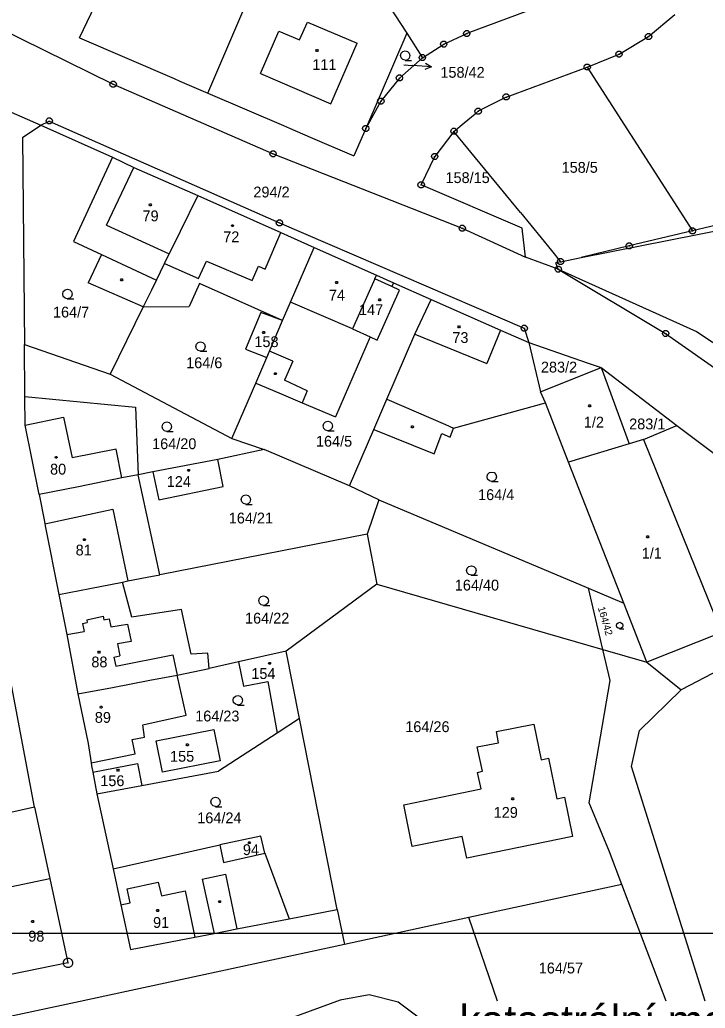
# Model space of a CAD drawing. Extents: x -779723 to -777378, y -1011169 to -1009297.
# Drawn here: x -779371.6 to -779263.9, y -1010279.6 to -1010124.4 of the extents above; entities that cross this region are included whole.
import ezdxf

# ---------------------------------------------------------------- set-up
doc = ezdxf.new("R2010")
doc.units = 0
for name, color, linetype in [('Default', 7, 'Continuous'), ('KN_HRANICE', 7, 'Continuous'), ('KN_KULTURY', 7, 'Continuous'), ('KN_PARCELY', 7, 'Continuous'), ('KN_SLUCKY', 7, 'Continuous'), ('LEGENDA', 7, 'Continuous')]:
    doc.layers.add(name, color=color, linetype=linetype)

# ---------------------------------------------------------------- blocks, each defined once
blk = doc.blocks.new('101')
at = {"layer": 'Default'}
blk.add_line((-0.05, 0), (0.05, 0), dxfattribs=at)
blk.add_lwpolyline([(0.19, 0.72), (0.53, 0.53), (0.72, 0.19), (0.72, -0.2), (0.53, -0.54), (0.19, -0.73), (-0.2, -0.73), (-0.54, -0.54), (-0.73, -0.2), (-0.73, 0.19), (-0.54, 0.53), (-0.2, 0.72), (0.19, 0.72)], dxfattribs=at)
blk = doc.blocks.new('304')
at = {"layer": 'Default'}
blk.add_lwpolyline([(0, 0), (-0.38, 0.1), (-0.65, 0.37), (-0.75, 0.74), (-0.65, 1.11), (-0.38, 1.38), (-0.01, 1.48), (0.36, 1.38), (0.63, 1.11), (0.73, 0.73), (0.63, 0.35), (0.36, 0.08), (-0.02, -0.02), (0.98, -0.02)], dxfattribs=at)
blk = doc.blocks.new('10292')
at = {"layer": 'Default'}
blk.add_line((0, 3), (0, 0), dxfattribs=at)
blk.add_lwpolyline([(-0.5, 2), (0, 3), (0.5, 2)], dxfattribs=at)
blk = doc.blocks.new('402')
at = {"layer": 'Default'}
blk.add_lwpolyline([(0.09, 0.15), (0.18, 0), (0.09, -0.15), (-0.09, -0.15), (-0.18, 0), (-0.09, 0.15), (0.09, 0.15)], dxfattribs=at)
blk = doc.blocks.new('105')
at = {"layer": 'Default'}
blk.add_line((-0.12, 0), (0.12, 0), dxfattribs=at)
blk.add_lwpolyline([(0.15, 0.48), (0.4, 0.3), (0.5, 0.01), (0.4, -0.28), (0.15, -0.46), (-0.16, -0.46), (-0.41, -0.28), (-0.51, 0.01), (-0.41, 0.3), (-0.16, 0.48), (0.15, 0.48)], dxfattribs=at)

msp = doc.modelspace()

# ---------------------------------------------------------------- linework, layer by layer
at = {"layer": 'KN_HRANICE'}
for p, q in [((-779362.17, -1010127.2), (-779340.06, -1010080.85)), ((-779342.01, -1010135.87), (-779327.06, -1010101.1)), ((-779327.06, -1010101.1), (-779310.76, -1010126.49)), ((-779288.77, -1010121.88), (-779301.33, -1010126.54)), ((-779380.8, -1010122.72), (-779356.88, -1010134.5)), ((-779272.77, -1010127.01), (-779268.62, -1010123.54)), ((-779327.61, -1010127.53), (-779326.36, -1010124.72)), ((-779326.36, -1010124.72), (-779318.57, -1010128.06)), ((-779333.75, -1010132.81), (-779330.83, -1010126.13)), ((-779330.83, -1010126.13), (-779327.61, -1010127.53)), ((-779310.76, -1010126.49), (-779317.19, -1010141.44)), ((-779310.76, -1010126.49), (-779308.3, -1010130.32)), ((-779304.94, -1010128.18), (-779301.33, -1010126.54)), ((-779277.41, -1010129.77), (-779272.77, -1010127.01)), ((-779308.3, -1010130.32), (-779304.94, -1010128.18)), ((-779282.4, -1010131.79), (-779277.41, -1010129.77)), ((-779308.3, -1010130.32), (-779311.9, -1010133.51)), ((-779295.13, -1010136.5), (-779282.4, -1010131.79)), ((-779282.4, -1010131.79), (-779265.87, -1010157.54)), ((-779356.88, -1010134.5), (-779331.75, -1010145.42)), ((-779311.9, -1010133.51), (-779314.82, -1010137.15)), ((-779379.75, -1010135.84), (-779368.25, -1010140.93)), ((-779314.82, -1010137.15), (-779317.19, -1010141.44)), ((-779295.13, -1010136.5), (-779299.54, -1010138.73)), ((-779301.73, -1010140.55), (-779300, -1010139.11)), ((-779300, -1010139.11), (-779299.54, -1010138.73)), ((-779371.12, -1010142.88), (-779368.25, -1010140.93)), ((-779368.25, -1010140.93), (-779356.99, -1010145.94)), ((-779303.34, -1010141.89), (-779301.73, -1010140.55)), ((-779317.19, -1010141.44), (-779319.05, -1010145.75)), ((-779303.34, -1010141.89), (-779306.36, -1010145.83)), ((-779292.91, -1010154.64), (-779303.34, -1010141.89)), ((-779371.12, -1010142.88), (-779370.81, -1010175.38)), ((-779331.75, -1010145.42), (-779302.03, -1010157.12)), ((-779356.99, -1010145.94), (-779363.09, -1010159.19)), ((-779356.99, -1010145.94), (-779353.64, -1010147.57)), ((-779308.49, -1010150.3), (-779306.36, -1010145.83)), ((-779353.64, -1010147.57), (-779343.57, -1010151.97)), ((-779225.76, -1010148.05), (-779265.87, -1010157.54)), ((-779292.63, -1010157.12), (-779308.49, -1010150.3)), ((-779283.36, -1010161.68), (-779225.71, -1010150.28)), ((-779343.57, -1010151.97), (-779346.34, -1010157.62)), ((-779343.57, -1010151.97), (-779330.56, -1010157.78)), ((-779292.91, -1010154.64), (-779288.01, -1010160.63)), ((-779346.34, -1010157.62), (-779348.07, -1010161.15)), ((-779330.56, -1010157.78), (-779325.31, -1010160.13)), ((-779302.03, -1010157.12), (-779292.12, -1010161.67)), ((-779292.12, -1010161.67), (-779292.63, -1010157.12)), ((-779265.87, -1010157.54), (-779275.8, -1010159.89)), ((-779363.09, -1010159.19), (-779358.72, -1010161.22)), ((-779348.79, -1010162.63), (-779348.07, -1010161.15)), ((-779329.01, -1010168.72), (-779325.31, -1010160.13)), ((-779325.31, -1010160.13), (-779315.53, -1010164.48)), ((-779288.01, -1010160.63), (-779286.59, -1010162.36)), ((-779275.8, -1010159.89), (-779283.36, -1010161.68)), ((-779358.72, -1010161.22), (-779360.82, -1010165.67)), ((-779350.07, -1010165.25), (-779348.79, -1010162.63)), ((-779286.95, -1010163.54), (-779292.12, -1010161.67)), ((-779286.59, -1010162.36), (-779287.32, -1010162.52)), ((-779286.95, -1010163.54), (-779287.32, -1010162.52)), ((-779286.59, -1010162.36), (-779283.36, -1010161.68)), ((-779286.95, -1010163.54), (-779270.09, -1010173.63)), ((-779286.95, -1010163.54), (-779265.26, -1010173.35)), ((-779352.15, -1010169.47), (-779360.82, -1010165.67)), ((-779350.37, -1010165.85), (-779350.86, -1010166.85)), ((-779350.07, -1010165.25), (-779350.37, -1010165.85)), ((-779343.34, -1010165.79), (-779344.96, -1010169.41)), ((-779330.25, -1010171.61), (-779343.34, -1010165.79)), ((-779315.79, -1010165.07), (-779319.28, -1010172.9)), ((-779313.09, -1010166.28), (-779315.79, -1010165.07)), ((-779315.53, -1010164.48), (-779312.82, -1010165.66)), ((-779312.82, -1010165.66), (-779313.09, -1010166.28)), ((-779312.82, -1010165.66), (-779306.92, -1010168.28)), ((-779350.86, -1010166.85), (-779352.15, -1010169.47)), ((-779315.38, -1010174.67), (-779311.89, -1010166.81)), ((-779311.89, -1010166.81), (-779313.09, -1010166.28)), ((-779330.25, -1010171.61), (-779329.01, -1010168.72)), ((-779309.48, -1010173.73), (-779306.92, -1010168.28)), ((-779306.92, -1010168.28), (-779296.03, -1010173.11)), ((-779352.15, -1010169.47), (-779357.33, -1010180.05)), ((-779352.15, -1010169.47), (-779344.96, -1010169.41)), ((-779332.31, -1010176.42), (-779330.25, -1010171.61)), ((-779319.28, -1010172.9), (-779316.5, -1010174.16)), ((-779296.03, -1010173.11), (-779291.6, -1010175.07)), ((-779265.26, -1010173.35), (-779254.75, -1010180.24)), ((-779316.5, -1010174.16), (-779321.95, -1010186.72)), ((-779316.5, -1010174.16), (-779315.38, -1010174.67)), ((-779313.9, -1010183.97), (-779309.48, -1010173.73)), ((-779291.6, -1010175.07), (-779289.74, -1010182.83)), ((-779270.09, -1010173.63), (-779257.16, -1010182.76)), ((-779370.73, -1010183.55), (-779370.81, -1010175.38)), ((-779370.81, -1010175.38), (-779357.33, -1010180.05)), ((-779332.74, -1010177.43), (-779332.31, -1010176.42)), ((-779334.46, -1010181.43), (-779332.74, -1010177.43)), ((-779289.74, -1010182.83), (-779280.19, -1010178.98)), ((-779280.19, -1010178.98), (-779268.33, -1010188.11)), ((-779280.19, -1010178.98), (-779275.82, -1010190.98)), ((-779357.33, -1010180.05), (-779338.22, -1010190.12)), ((-779338.22, -1010190.12), (-779334.46, -1010181.43)), ((-779334.46, -1010181.43), (-779330.86, -1010182.95)), ((-779288.98, -1010184.55), (-779289.74, -1010182.83)), ((-779370.69, -1010188.04), (-779370.73, -1010183.55)), ((-779370.73, -1010183.55), (-779353.39, -1010185.24)), ((-779330.86, -1010182.95), (-779327.18, -1010184.51)), ((-779315.95, -1010188.73), (-779313.9, -1010183.97)), ((-779353.39, -1010185.24), (-779352.97, -1010195.83)), ((-779327.18, -1010184.51), (-779321.95, -1010186.72)), ((-779303.42, -1010188.49), (-779288.98, -1010184.55)), ((-779285.33, -1010193.87), (-779288.98, -1010184.55)), ((-779368.51, -1010198.95), (-779370.69, -1010188.04)), ((-779319.77, -1010197.59), (-779315.95, -1010188.73)), ((-779315.95, -1010188.73), (-779306.46, -1010192.53)), ((-779303.95, -1010189.91), (-779303.42, -1010188.49)), ((-779273.57, -1010190.29), (-779268.33, -1010188.11)), ((-779268.33, -1010188.11), (-779262.24, -1010192.63)), ((-779338.22, -1010190.12), (-779333.16, -1010191.86)), ((-779306.46, -1010192.53), (-779305.24, -1010189.37)), ((-779305.24, -1010189.37), (-779303.95, -1010189.91)), ((-779273.57, -1010190.29), (-779275.82, -1010190.98)), ((-779273.57, -1010190.29), (-779261.29, -1010220.59)), ((-779333.16, -1010191.86), (-779340.44, -1010193.45)), ((-779319.77, -1010197.59), (-779333.16, -1010191.86)), ((-779275.82, -1010190.98), (-779285.33, -1010193.87)), ((-779340.44, -1010193.45), (-779350.63, -1010195.35)), ((-779339.6, -1010197.69), (-779340.44, -1010193.45)), ((-779350.63, -1010195.35), (-779352.97, -1010195.83)), ((-779350.63, -1010195.35), (-779349.69, -1010199.77)), ((-779276.66, -1010216.01), (-779285.33, -1010193.87)), ((-779355.52, -1010196.34), (-779362.33, -1010197.71)), ((-779352.97, -1010195.83), (-779355.52, -1010196.34)), ((-779349.54, -1010211.54), (-779352.97, -1010195.83)), ((-779362.33, -1010197.71), (-779368.51, -1010198.95)), ((-779349.69, -1010199.77), (-779339.6, -1010197.69)), ((-779315.16, -1010199.77), (-779319.77, -1010197.59)), ((-779315.16, -1010199.77), (-779317, -1010205.16)), ((-779315.16, -1010199.77), (-779282.2, -1010213.67)), ((-779317, -1010205.16), (-779349.54, -1010211.54)), ((-779317, -1010205.16), (-779315.47, -1010213.01)), ((-779354.59, -1010212.5), (-779351.55, -1010211.93)), ((-779351.55, -1010211.93), (-779349.54, -1010211.54)), ((-779365.42, -1010214.66), (-779360.52, -1010213.7)), ((-779360.52, -1010213.7), (-779355.42, -1010212.7)), ((-779355.42, -1010212.7), (-779354.59, -1010212.5)), ((-779353.94, -1010218.2), (-779355.42, -1010212.7)), ((-779315.47, -1010213.01), (-779329.68, -1010223.56)), ((-779315.47, -1010213.01), (-779279.96, -1010223.28)), ((-779282.2, -1010213.67), (-779276.66, -1010216.01)), ((-779279.96, -1010223.28), (-779282.2, -1010213.67)), ((-779365.42, -1010214.66), (-779364.16, -1010220.93)), ((-779346.13, -1010216.99), (-779353.94, -1010218.2)), ((-779344.62, -1010224.02), (-779346.13, -1010216.99)), ((-779273.03, -1010225.28), (-779276.66, -1010216.01)), ((-779364.16, -1010220.93), (-779362.43, -1010230.27)), ((-779261.29, -1010220.59), (-779273.03, -1010225.28)), ((-779250.45, -1010220.64), (-779267.64, -1010229.61)), ((-779279.96, -1010223.28), (-779273.03, -1010225.28)), ((-779278.82, -1010228.15), (-779279.96, -1010223.28)), ((-779342.02, -1010223.87), (-779344.62, -1010224.02)), ((-779341.78, -1010226.26), (-779342.02, -1010223.87)), ((-779329.68, -1010223.56), (-779337.17, -1010225.23)), ((-779327.59, -1010234.13), (-779329.68, -1010223.56)), ((-779346.83, -1010227.29), (-779341.78, -1010226.26)), ((-779337.17, -1010225.23), (-779341.78, -1010226.26)), ((-779273.03, -1010225.28), (-779267.64, -1010229.61)), ((-779351.1, -1010228.1), (-779346.83, -1010227.29)), ((-779369.26, -1010248.05), (-779372.96, -1010228.31)), ((-779362.43, -1010230.27), (-779356.99, -1010229.23)), ((-779356.99, -1010229.23), (-779351.1, -1010228.1)), ((-779282.1, -1010247.39), (-779278.82, -1010228.15)), ((-779362.43, -1010230.27), (-779360.81, -1010238.06)), ((-779274.18, -1010236), (-779267.64, -1010229.61)), ((-779327.59, -1010234.13), (-779331.1, -1010236.4)), ((-779321.68, -1010264.11), (-779327.59, -1010234.13)), ((-779296.68, -1010236.16), (-779290.77, -1010235.01)), ((-779290.77, -1010235.01), (-779289.63, -1010240.6)), ((-779331.1, -1010236.4), (-779340.34, -1010242.39)), ((-779296.34, -1010237.93), (-779296.68, -1010236.16)), ((-779275.45, -1010241.64), (-779274.18, -1010236)), ((-779360.81, -1010238.06), (-779360.33, -1010241.1)), ((-779299.67, -1010238.58), (-779296.34, -1010237.93)), ((-779298.86, -1010242.42), (-779299.67, -1010238.58)), ((-779289.63, -1010240.6), (-779288.47, -1010240.36)), ((-779288.47, -1010240.36), (-779287.16, -1010246.73)), ((-779360.33, -1010241.1), (-779360.26, -1010241.57)), ((-779360.26, -1010241.57), (-779360.07, -1010242.55)), ((-779263.9, -1010278.51), (-779275.45, -1010241.64)), ((-779360.07, -1010242.55), (-779359.42, -1010245.98)), ((-779352.38, -1010244.66), (-779340.34, -1010242.39)), ((-779299.63, -1010242.58), (-779298.86, -1010242.42)), ((-779299.09, -1010245.15), (-779299.63, -1010242.58)), ((-779359.42, -1010245.98), (-779352.38, -1010244.66)), ((-779359.42, -1010245.98), (-779356.9, -1010257.72)), ((-779311.24, -1010247.7), (-779299.09, -1010245.15)), ((-779287.16, -1010246.73), (-779285.99, -1010246.49)), ((-779285.99, -1010246.49), (-779284.72, -1010252.66)), ((-779369.26, -1010248.05), (-779389.34, -1010252.55)), ((-779369.26, -1010248.05), (-779366.85, -1010259.23)), ((-779309.89, -1010254.22), (-779311.24, -1010247.7)), ((-779278.89, -1010255.08), (-779282.1, -1010247.39)), ((-779333.7, -1010252.59), (-779340.13, -1010253.99)), ((-779333.07, -1010255.29), (-779333.7, -1010252.59)), ((-779302.06, -1010252.64), (-779309.89, -1010254.22)), ((-779301.34, -1010256.04), (-779302.06, -1010252.64)), ((-779284.72, -1010252.66), (-779301.34, -1010256.04)), ((-779356.9, -1010257.72), (-779340.13, -1010253.99)), ((-779340.13, -1010253.99), (-779339.57, -1010256.76)), ((-779339.57, -1010256.76), (-779333.07, -1010255.29)), ((-779333.07, -1010255.29), (-779329.22, -1010265.58)), ((-779276.95, -1010260.2), (-779278.89, -1010255.08)), ((-779356.9, -1010257.72), (-779355.68, -1010263.39)), ((-779375.67, -1010261.12), (-779366.85, -1010259.23)), ((-779366.85, -1010259.23), (-779363.99, -1010272.5)), ((-779276.95, -1010260.2), (-779300.99, -1010265.39)), ((-779270, -1010278.51), (-779276.95, -1010260.2)), ((-779355.68, -1010263.39), (-779354.17, -1010270.43)), ((-779329.22, -1010265.58), (-779321.68, -1010264.11)), ((-779321.68, -1010264.11), (-779320.52, -1010269.6)), ((-779337.47, -1010267.18), (-779329.22, -1010265.58)), ((-779300.99, -1010265.39), (-779320.52, -1010269.6)), ((-779296.52, -1010278.51), (-779300.99, -1010265.39)), ((-779344.05, -1010268.46), (-779341.01, -1010267.87)), ((-779341.01, -1010267.87), (-779337.47, -1010267.18)), ((-779320.52, -1010269.6), (-779362.78, -1010278.71)), ((-779354.17, -1010270.43), (-779344.05, -1010268.46)), ((-779363.99, -1010272.5), (-779372.96, -1010274.36)), ((-779316.65, -1010277.51), (-779321.24, -1010278.36)), ((-779312.1, -1010278.67), (-779316.65, -1010277.51)), ((-779362.78, -1010278.71), (-779411.57, -1010289.24)), ((-779321.24, -1010278.36), (-779338.14, -1010284.55)), ((-779308.36, -1010281.51), (-779312.1, -1010278.67))]:
    msp.add_line(p, q, dxfattribs=at)
for points in [[(-779362.17, -1010127.2), (-779347.32, -1010133.59), (-779346.4, -1010133.98), (-779342.01, -1010135.87)], [(-779333.75, -1010132.81), (-779322.68, -1010137.57), (-779318.57, -1010128.06)], [(-779342.01, -1010135.87), (-779330.11, -1010140.99), (-779329.19, -1010141.39), (-779325.94, -1010142.79), (-779319.05, -1010145.75)], [(-779330.25, -1010171.61), (-779333.7, -1010170.34), (-779336.07, -1010176.09), (-779332.74, -1010177.43)], [(-779291.6, -1010175.07), (-779282.25, -1010178.28), (-779280.19, -1010178.98)], [(-779368.51, -1010198.95), (-779367.68, -1010203.17), (-779367.63, -1010203.52)], [(-779367.63, -1010203.52), (-779367.55, -1010203.87), (-779365.42, -1010214.66)], [(-779337.17, -1010225.23), (-779336.4, -1010229.03), (-779332.59, -1010228.29), (-779331.1, -1010236.4)], [(-779360.33, -1010241.1), (-779353.42, -1010239.67), (-779353.88, -1010237.43), (-779351.94, -1010237.03), (-779352.2, -1010235.13), (-779345.41, -1010233.6), (-779346.83, -1010227.29)], [(-779360.07, -1010242.55), (-779353.08, -1010241.18), (-779352.38, -1010244.66)]]:
    msp.add_lwpolyline(points, dxfattribs=at)
msp.add_lwpolyline([(-779350.1, -1010237.63), (-779341.04, -1010235.87), (-779340.09, -1010240.76), (-779349.15, -1010242.54)], close=True, dxfattribs=at)
at = {"layer": 'KN_PARCELY'}
msp.add_line((-779311.2, -1010131.45), (-779309.85, -1010131.55), dxfattribs=at)
at = {"layer": 'KN_SLUCKY'}
for p, q in [((-779368.25, -1010140.93), (-779366.91, -1010140.27)), ((-779366.91, -1010140.27), (-779330.75, -1010156.28)), ((-779357.95, -1010156.63), (-779353.64, -1010147.57)), ((-779330.75, -1010156.28), (-779292.29, -1010172.82)), ((-779357.95, -1010156.63), (-779348.07, -1010161.15)), ((-779333.01, -1010163.53), (-779330.56, -1010157.78)), ((-779358.72, -1010161.22), (-779350.07, -1010165.25)), ((-779334.03, -1010163.08), (-779333.01, -1010163.53)), ((-779315.79, -1010165.07), (-779315.53, -1010164.48)), ((-779319.28, -1010172.9), (-779329.01, -1010168.72)), ((-779296.03, -1010173.11), (-779298.16, -1010178.34)), ((-779292.29, -1010172.82), (-779291.6, -1010175.07)), ((-779309.48, -1010173.73), (-779298.16, -1010178.34)), ((-779328.64, -1010178), (-779332.31, -1010176.42)), ((-779328.64, -1010178), (-779329.98, -1010180.98)), ((-779326.39, -1010182.67), (-779329.98, -1010180.98)), ((-779326.39, -1010182.67), (-779327.18, -1010184.51)), ((-779313.9, -1010183.97), (-779304.69, -1010187.94)), ((-779370.69, -1010188.04), (-779364.7, -1010186.76)), ((-779364.7, -1010186.76), (-779363.31, -1010193.19)), ((-779304.69, -1010187.94), (-779303.42, -1010188.49)), ((-779356.41, -1010191.83), (-779363.31, -1010193.19)), ((-779355.52, -1010196.34), (-779356.41, -1010191.83)), ((-779362.74, -1010202.49), (-779356.94, -1010201.26)), ((-779356.94, -1010201.26), (-779354.59, -1010212.5)), ((-779367.63, -1010203.52), (-779362.74, -1010202.49)), ((-779361.03, -1010218.61), (-779358.43, -1010218.07)), ((-779361.03, -1010218.61), (-779360.95, -1010219.06)), ((-779358.43, -1010218.07), (-779358.32, -1010218.61)), ((-779358.32, -1010218.61), (-779357.53, -1010218.47)), ((-779357.53, -1010218.47), (-779357.27, -1010219.74)), ((-779361.69, -1010219.18), (-779360.95, -1010219.06)), ((-779361.69, -1010219.18), (-779361.45, -1010220.46)), ((-779357.27, -1010219.74), (-779354.61, -1010219.28)), ((-779354.61, -1010219.28), (-779354.07, -1010222.04)), ((-779364.16, -1010220.93), (-779361.45, -1010220.46)), ((-779354.07, -1010222.04), (-779356.19, -1010222.38)), ((-779356.19, -1010222.38), (-779355.84, -1010224.3)), ((-779356.77, -1010224.47), (-779355.84, -1010224.3)), ((-779356.77, -1010224.47), (-779356.45, -1010225.88)), ((-779356.45, -1010225.88), (-779347.53, -1010224.13)), ((-779347.53, -1010224.13), (-779346.83, -1010227.29)), ((-779342.88, -1010259.37), (-779339.21, -1010258.56)), ((-779339.21, -1010258.56), (-779337.47, -1010267.18)), ((-779354.69, -1010260.87), (-779349.8, -1010259.81)), ((-779349.8, -1010259.81), (-779349.27, -1010261.99)), ((-779342.88, -1010259.37), (-779341.01, -1010267.87)), ((-779354.22, -1010263.07), (-779354.69, -1010260.87)), ((-779349.27, -1010261.99), (-779345.55, -1010261.19)), ((-779345.55, -1010261.19), (-779344.05, -1010268.46)), ((-779355.68, -1010263.39), (-779354.22, -1010263.07))]:
    msp.add_line(p, q, dxfattribs=at)
msp.add_lwpolyline([(-779348.79, -1010162.63), (-779343.48, -1010165.02), (-779342.22, -1010162.27), (-779335.04, -1010165.34), (-779334.03, -1010163.08)], dxfattribs=at)
at = {"layer": 'LEGENDA'}
msp.add_lwpolyline([(-779530.66, -1010687.91), (-778936.66, -1010687.91), (-778936.66, -1010267.91), (-779530.66, -1010267.91)], close=True, dxfattribs=at)

# ---------------------------------------------------------------- block references
at = {"layer": 'KN_KULTURY'}
for name, p in [('402', (-779324.85, -1010129.2)), ('304', (-779311.01, -1010130.72)), ('402', (-779351.06, -1010153.44)), ('402', (-779338.13, -1010156.71)), ('402', (-779355.54, -1010165.23)), ('402', (-779321.77, -1010165.65)), ('304', (-779364.06, -1010168.18)), ('402', (-779315, -1010168.37)), ('402', (-779333.24, -1010173.47)), ('402', (-779302.56, -1010172.59)), ('304', (-779343.14, -1010176.42)), ('402', (-779331.38, -1010179.95)), ('402', (-779282.01, -1010184.99)), ('304', (-779348.44, -1010189.02)), ('304', (-779323.14, -1010188.91)), ('402', (-779309.86, -1010188.31)), ('402', (-779365.83, -1010193.09)), ('402', (-779345.02, -1010195.14)), ('304', (-779297.4, -1010196.88)), ('304', (-779336.02, -1010200.47)), ('402', (-779361.39, -1010206.03)), ('402', (-779272.91, -1010205.57)), ('304', (-779300.6, -1010211.61)), ('304', (-779333.23, -1010216.35)), ('402', (-779359.1, -1010223.72)), ('402', (-779332.31, -1010225.46)), ('304', (-779337.3, -1010231.99)), ('402', (-779358.76, -1010232.33)), ('402', (-779345.21, -1010238.26)), ('402', (-779356.13, -1010242.24)), ('304', (-779340.79, -1010247.96)), ('402', (-779294.12, -1010246.74)), ('402', (-779335.49, -1010253.62)), ('402', (-779340.15, -1010262.9)), ('402', (-779349.9, -1010264.27)), ('402', (-779369.54, -1010266.01))]:
    msp.add_blockref(name, p, dxfattribs=at)
at = {"layer": 'KN_KULTURY', "xscale": 0.67, "yscale": 0.67}
msp.add_blockref('304', (-779277.3, -1010220), dxfattribs=at)
at = {"layer": 'KN_PARCELY'}
for name, p in [('105', (-779301.33, -1010126.54)), ('105', (-779272.77, -1010127.01)), ('105', (-779304.94, -1010128.18)), ('105', (-779308.3, -1010130.32)), ('105', (-779277.41, -1010129.77)), ('105', (-779282.4, -1010131.79)), ('105', (-779311.9, -1010133.51)), ('105', (-779356.88, -1010134.5)), ('105', (-779295.13, -1010136.5)), ('105', (-779314.82, -1010137.15)), ('105', (-779299.54, -1010138.73)), ('105', (-779366.91, -1010140.27)), ('105', (-779317.19, -1010141.44)), ('105', (-779303.34, -1010141.89)), ('105', (-779331.75, -1010145.42)), ('105', (-779306.36, -1010145.83)), ('105', (-779308.49, -1010150.3)), ('105', (-779330.75, -1010156.28)), ('105', (-779302.03, -1010157.12)), ('105', (-779265.87, -1010157.54)), ('105', (-779275.8, -1010159.89)), ('105', (-779286.59, -1010162.36)), ('105', (-779286.95, -1010163.54)), ('105', (-779292.29, -1010172.82)), ('105', (-779270.09, -1010173.63)), ('101', (-779363.97, -1010272.51))]:
    msp.add_blockref(name, p, dxfattribs=at)
at = {"layer": 'KN_PARCELY', "rotation": -94.20487900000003}
msp.add_blockref('10292', (-779309.85, -1010131.55), dxfattribs=at)

# ---------------------------------------------------------------- texts
at = {"layer": 'KN_PARCELY'}
for s, height, p in [('111', 1.7, (-779325.59, -1010132.25)), ('158/42', 0.1, (-779311.18, -1010131.45)), ('158/42', 1.7, (-779305.47, -1010133.47)), ('158/5', 1.7, (-779286.43, -1010148.4)), ('158/15', 1.7, (-779304.67, -1010150.01)), ('294/2', 1.7, (-779334.85, -1010152.27)), ('79', 1.7, (-779352.27, -1010156.02)), ('72', 1.7, (-779339.59, -1010159.3)), ('74', 1.7, (-779322.99, -1010168.47)), ('164/7', 1.7, (-779366.33, -1010171.13)), ('147', 1.7, (-779318.25, -1010170.75)), ('73', 1.7, (-779303.59, -1010175.13)), ('158', 1.7, (-779334.69, -1010175.78)), ('164/6', 1.7, (-779345.41, -1010179.09)), ('283/2', 1.7, (-779289.68, -1010179.77)), ('1/2', 1.7, (-779282.94, -1010188.42)), ('283/1', 1.7, (-779275.82, -1010188.7)), ('164/20', 1.7, (-779350.76, -1010191.81)), ('164/5', 1.7, (-779325.02, -1010191.42)), ('80', 1.7, (-779366.79, -1010195.8)), ('124', 1.7, (-779348.46, -1010197.75)), ('164/4', 1.7, (-779299.55, -1010199.81)), ('164/21', 1.7, (-779338.72, -1010203.48)), ('81', 1.7, (-779362.77, -1010208.51)), ('1/1', 1.7, (-779273.84, -1010209)), ('164/40', 1.7, (-779303.21, -1010214.02)), ('164/22', 1.7, (-779336.16, -1010219.21)), ('88', 1.7, (-779360.3, -1010226.09)), ('154', 1.7, (-779335.17, -1010227.91)), ('89', 1.7, (-779359.76, -1010234.8)), ('164/23', 1.7, (-779343.99, -1010234.58)), ('164/26', 1.7, (-779310.99, -1010236.26)), ('155', 1.7, (-779347.94, -1010240.91)), ('156', 1.7, (-779358.9, -1010244.75)), ('129', 1.7, (-779297.1, -1010249.72)), ('164/24', 1.7, (-779343.67, -1010250.58)), ('94', 1.7, (-779336.5, -1010255.58)), ('91', 1.7, (-779350.61, -1010267.01)), ('98', 1.7, (-779370.22, -1010269.17)), ('164/57', 1.7, (-779290.02, -1010274.17))]:
    msp.add_text(s, height=height, dxfattribs=at).set_placement(p)
msp.add_text('164/42', height=1.14, rotation=286.135, dxfattribs=at).set_placement((-779280.76, -1010216.72))
at = {"layer": 'LEGENDA'}
msp.add_text('katastrální mapa Vlčí u Chlumčan', height=5, dxfattribs=at).set_placement((-779302.48, -1010284.12))

doc.saveas('drawing.dxf')
